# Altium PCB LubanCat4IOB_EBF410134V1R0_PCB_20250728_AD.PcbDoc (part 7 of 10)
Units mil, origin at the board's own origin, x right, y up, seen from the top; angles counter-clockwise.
Board outline 5236.21 x 4055.11 mil, 6 copper layers (TOP, GND02, ART03, PWR04, GND05, BOTTOM), stack 47.2 mil thick; 614 components, 490 nets, 2311 pads, 1916 vias.
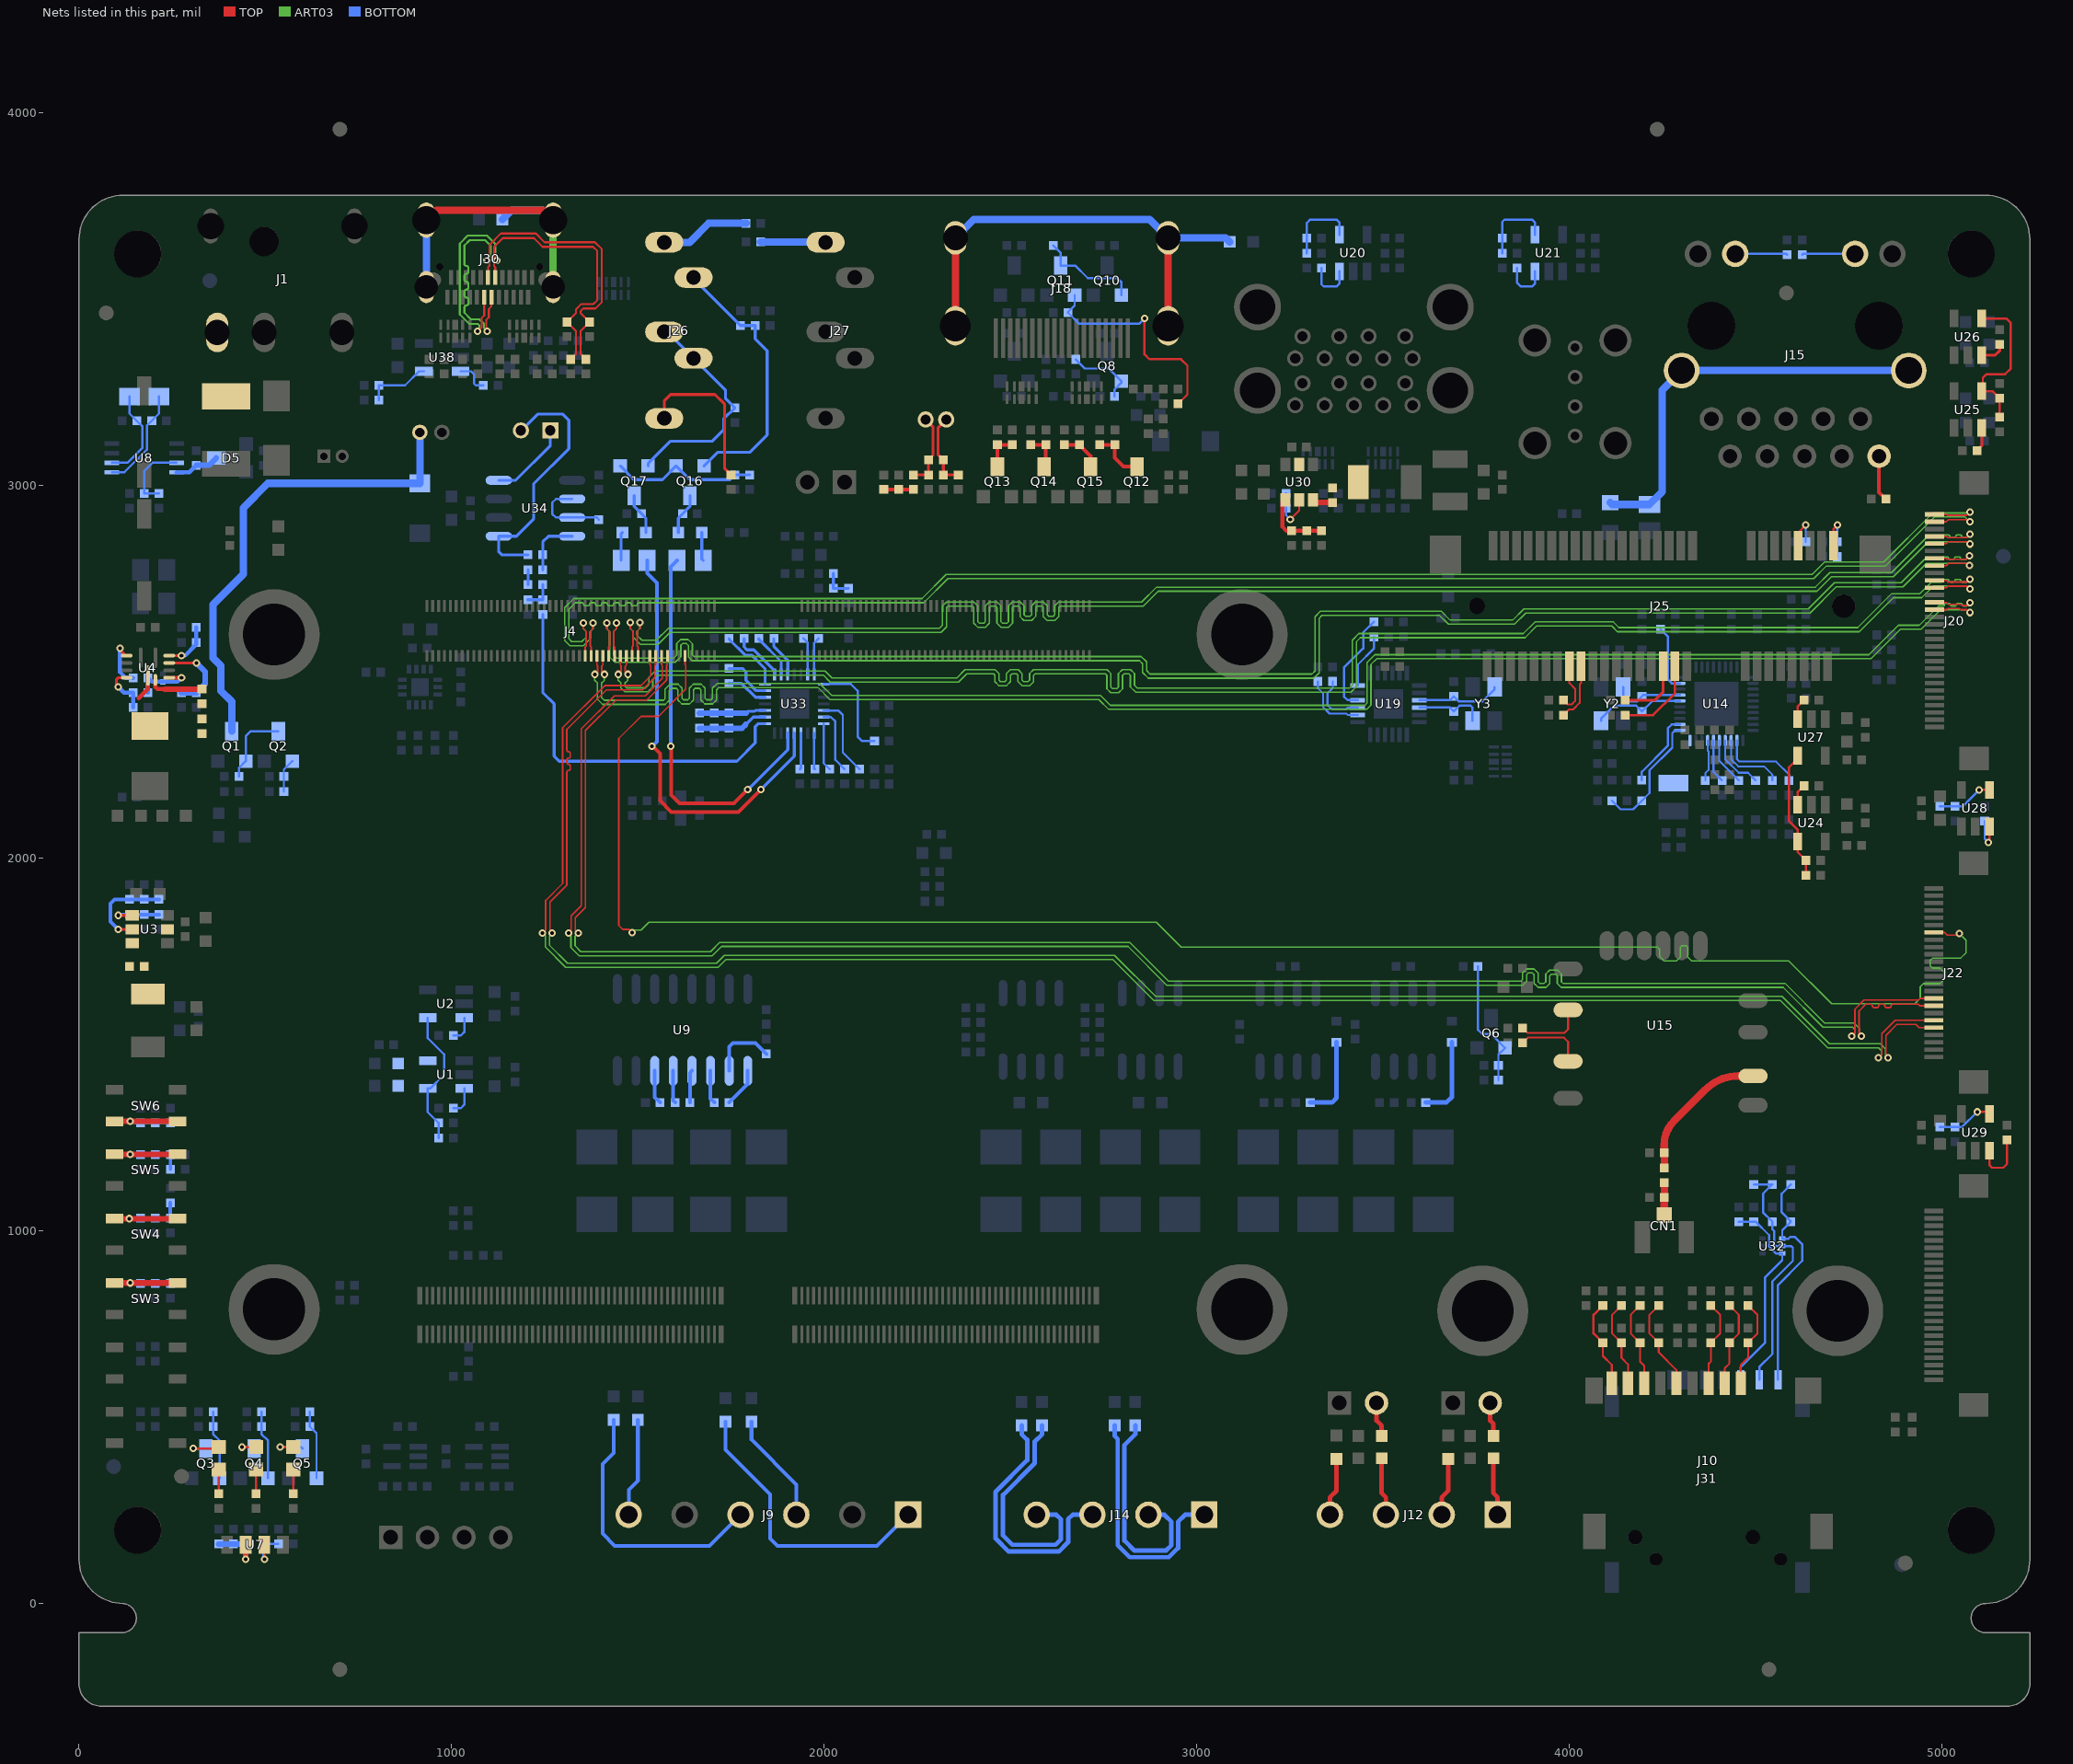
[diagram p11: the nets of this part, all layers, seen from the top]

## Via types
v1: diameter 20, hole 10, TOP to BOTTOM, 1912 vias
v2: diameter 40/50/50/50/50/40 (per signal layer), hole 0, TOP to BOTTOM, 4 vias

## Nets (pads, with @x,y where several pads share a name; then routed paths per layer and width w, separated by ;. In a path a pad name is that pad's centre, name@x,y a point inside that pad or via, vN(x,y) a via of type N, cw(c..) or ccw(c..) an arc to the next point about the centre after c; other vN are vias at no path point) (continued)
MIPI_DPHY1_RX_D1P: J4.89 J22.7 | length 4930.3
  TOP w4.2: v1(1485,1800.77) 1476.6,1809.17 1459.56,1809.17 1448.8,1819.93 1448.8,2321.41 1508.36,2380.97 1555.76,2380.97 1628.74,2453.95 1628.74,2517.7 1626.46,2519.97 J4.89@1626.46,2543.51 ; J22.7@4978.61,1801.18 5007.19,1801.18 5014.74,1793.63 5041.88,1793.63 v1(5046.59,1798.34)
  ART03 w4: v1(1485,1800.77) 1491.6,1807.37 1508.56,1807.37 1529.56,1828.37 2891.44,1828.37 2958.44,1761.37 4236.84,1761.37 4242.6,1755.61 4242.6,1736.41 4254.64,1724.37 4287.68,1724.37 4298.12,1734.81 4298.12,1761.17 4302.12,1765.17 4314.12,1765.17 4318.12,1761.17 4318.12,1734.81 4328.57,1724.37 4589.04,1724.37 4704.04,1609.37 4927.56,1609.37 4942,1623.81 4942,1655.37 4950,1663.37 4994.76,1663.37 5005.2,1673.81 5005.2,1694.93 4994.76,1705.37 4974.6,1705.37 4968.6,1711.37 4968.6,1725.57 4975.4,1732.37 5050.8,1732.37 5064.59,1746.16 5064.59,1780.34 v1(5046.59,1798.34)
MIPI_DPHY1_RX_D2N: J4.83 J22.17 | length 4925.6
  TOP w4.2: v1(1339.8,1799.37) 1332,1807.17 1332,1840.53 1359.4,1867.93 1359.4,2342.97 1441.2,2424.77 1523.99,2424.77 1576.95,2477.72 1576.95,2517.7 1579.22,2519.97 J4.83@1579.22,2543.51 ; v1(4784.1,1522.47) 4777.8,1528.77 4777.8,1590.33 4795.68,1608.21 4809.05,1608.21 cw(c4809.05,1603.69) 4813.57,1603.69 ccw(c4818.09,1603.69) 4818.09,1599.17 4825.85,1599.17 ccw(c4825.85,1603.69) 4830.37,1603.69 cw(c4834.89,1603.69) 4834.89,1608.21 4842.65,1608.21 cw(c4842.65,1603.69) 4847.17,1603.69 ccw(c4851.69,1603.69) 4851.69,1599.17 4859.45,1599.17 ccw(c4859.45,1603.69) 4863.97,1603.69 cw(c4868.49,1603.69) 4868.49,1608.21 4936.56,1608.21 4940.44,1604.33 J22.17@4978.61,1604.33
  ART03 w4: v1(1339.8,1799.37) 1331.3,1790.87 1331.3,1765.07 1347,1749.37 1695,1749.37 1720,1774.37 2820.16,1774.37 2924.16,1670.37 3870.78,1670.37 3874.78,1674.37 3874.78,1692.53 3885.22,1702.97 3905.74,1702.97 3916.78,1691.93 3916.78,1668.37 3920.78,1664.37 3932.78,1664.37 3936.78,1668.37 3936.78,1689.33 3947.22,1699.77 3968.34,1699.77 3978.78,1689.33 3978.78,1668.37 3982.78,1664.37 4578.8,1664.37 4685.8,1557.37 4765,1557.37 4778.6,1543.77 4778.6,1527.97 v1(4784.1,1522.47)
MIPI_DPHY1_RX_D2P: J4.81 J22.16 | length 4925.2
  TOP w4.2: v1(1313.8,1799.37) 1320.8,1806.37 1320.8,1845.17 1348.2,1872.57 1348.2,2347.61 1436.56,2435.97 1519.35,2435.97 1565.75,2482.36 1565.75,2517.7 1563.47,2519.97 J4.81@1563.47,2543.51 ; v1(4758.1,1522.47) 4766.6,1530.97 4766.6,1594.97 4791.04,1619.41 4937.04,1619.41 4941.64,1624.01 J22.16@4978.61,1624.01
  ART03 w4: v1(1313.8,1799.37) 1320.3,1792.87 1320.3,1760.51 1342.44,1738.37 1699.56,1738.37 1724.56,1763.37 2815.6,1763.37 2919.6,1659.37 3875.34,1659.37 3885.78,1669.81 3885.78,1687.97 3889.78,1691.97 3901.18,1691.97 3905.78,1687.37 3905.78,1663.81 3916.22,1653.37 3937.34,1653.37 3947.78,1663.81 3947.78,1684.77 3951.78,1688.77 3963.78,1688.77 3967.78,1684.77 3967.78,1663.81 3978.22,1653.37 4574.24,1653.37 4681.24,1546.37 4760.44,1546.37 4767.6,1539.21 4767.6,1531.97 v1(4758.1,1522.47)
MIPI_DPHY1_RX_D3N: J4.79 J22.20 | length 4930.2
  TOP w4.2: v1(1270,1799.37) 1263.8,1805.57 1263.8,1882.33 1309.4,1927.93 1309.4,2231.04 cw(c1313.9,2231.04) 1313.9,2235.54 ccw(c1313.9,2240.04) 1318.4,2240.04 1318.4,2247.84 ccw(c1313.9,2247.84) 1313.9,2252.34 cw(c1313.9,2256.84) 1309.4,2256.84 1309.4,2264.64 cw(c1313.9,2264.64) 1313.9,2269.14 ccw(c1313.9,2273.64) 1318.4,2273.64 1318.4,2281.44 ccw(c1313.9,2281.44) 1313.9,2285.94 cw(c1313.9,2290.44) 1309.4,2290.44 1309.4,2346.17 1415.4,2452.17 1512.64,2452.17 1545.45,2484.98 1545.45,2517.7 1547.72,2519.97 J4.79@1547.72,2543.51 ; v1(4856,1464.37) 4850.2,1470.17 4850.2,1524.73 4879.23,1553.76 4930.61,1553.76 4939.1,1545.27 J22.20@4978.61,1545.27
  ART03 w4: v1(1270,1799.37) 1262.5,1791.87 1262.5,1766.87 1311,1718.37 1711,1718.37 1732,1739.37 2779.56,1739.37 2889.56,1629.37 4571,1629.37 4698.2,1502.17 4835.03,1502.17 4849,1488.2 4849,1471.37 v1(4856,1464.37)
MIPI_DPHY1_RX_D3P: J4.77 J22.19 | length 4927.4
  TOP w4.2: v1(1244,1799.37) 1252.6,1807.97 1252.6,1886.97 1298.2,1932.57 1298.2,2350.81 1410.76,2463.37 1508,2463.37 1534.25,2489.62 1534.25,2517.7 1531.97,2519.97 J4.77@1531.97,2543.51 ; v1(4830,1464.37) 4839,1473.37 4839,1529.37 4874.59,1564.96 J22.19@4978.61,1564.96
  ART03 w4: v1(1244,1799.37) 1251.5,1791.87 1251.5,1762.31 1306.44,1707.37 1715.56,1707.37 1736.56,1728.37 2775,1728.37 2885,1618.37 4566.44,1618.37 4693.64,1491.17 4830.48,1491.17 4838,1483.65 4838,1472.37 v1(4830,1464.37)
MIPI_DPHY1_TX_CLKN: J4.65 J20.24 | length 4284.1
  TOP w4.2: J4.65@1437.49,2543.51 1437.49,2567.06 1435.21,2569.33 1435.21,2608.39 1442.61,2615.79 v1(1442.61,2631.44) ; J20.24@4980.62,2804.92 5012.08,2804.92 5014.13,2802.87 5065.55,2802.87 5074.5,2811.82 v1(5074.5,2812.22)
  ART03 w4: v1(1442.61,2631.44) 1442.61,2615.81 1435.11,2608.31 1435.11,2544.86 1443.4,2536.57 1595.58,2536.57 1604.38,2545.37 1604.38,2576.73 1614.83,2587.17 1634.94,2587.17 1646.38,2575.73 1646.38,2545.37 1650.38,2541.37 2851,2541.37 2865.4,2526.97 2865.4,2503.37 2874.4,2494.37 3309.4,2494.37 3317.4,2502.37 3317.4,2648.53 3331.84,2662.97 3656.36,2662.97 3680.16,2639.17 3848.24,2639.17 3878.44,2669.37 4641.64,2669.37 4711.64,2739.37 4891,2739.37 4954,2802.37 4999.06,2802.37 ccw(c4999.06,2805.47) 5002.16,2805.47 cw(c5005.26,2805.47) 5005.26,2808.57 5015.06,2808.57 cw(c5015.06,2805.47) 5018.16,2805.47 ccw(c5021.26,2805.47) 5021.26,2802.37 5031.06,2802.37 ccw(c5031.06,2805.47) 5034.16,2805.47 cw(c5037.26,2805.47) 5037.26,2808.57 5047.06,2808.57 cw(c5047.06,2805.47) 5050.16,2805.47 ccw(c5053.26,2805.47) 5053.26,2802.37 5065.19,2802.37 5074.5,2811.68 v1(5074.5,2812.22)
MIPI_DPHY1_TX_CLKP: J4.63 J20.23 | length 4285.9
  TOP w4.2: v1(1416.61,2631.44) 1416.61,2615.79 1424.01,2608.39 1424.01,2569.33 1421.74,2567.06 J4.63@1421.74,2543.51 ; J20.23@4980.62,2785.23 5011.86,2785.23 5018.3,2791.67 5069.05,2791.67 v1(5074.5,2786.22)
  ART03 w4: v1(1416.61,2631.44) 1416.61,2615.81 1424.11,2608.31 1424.11,2540.3 1438.84,2525.57 1600.14,2525.57 1615.38,2540.81 1615.38,2572.17 1619.38,2576.17 1630.38,2576.17 1635.38,2571.17 1635.38,2540.81 1645.83,2530.37 2846.44,2530.37 2854.4,2522.41 2854.4,2498.81 2869.84,2483.37 3313.96,2483.37 3328.4,2497.81 3328.4,2643.97 3336.4,2651.97 3651.8,2651.97 3675.6,2628.17 3852.8,2628.17 3883,2658.37 4646.2,2658.37 4716.2,2728.37 4895.56,2728.37 4958.56,2791.37 5065.71,2791.37 5068.71,2788.37 5070.5,2788.37 5072.65,2786.22 v1(5074.5,2786.22)
MIPI_DPHY1_TX_D0N: J4.73 J20.27 | length 4288.8
  TOP w4.2: J4.73@1500.48,2543.51 1500.48,2567.06 1498.2,2569.33 1498.2,2609.32 1505.61,2616.72 v1(1505.61,2632.37) ; J20.27@4980.62,2863.97 5012.08,2863.97 5015.32,2860.73 5066.36,2860.73 v1(5075,2869.37)
  ART03 w4: v1(1505.61,2632.37) 1505.61,2616.74 1498.11,2609.24 1498.11,2598.37 1511.31,2585.17 1549.64,2585.17 1581.84,2617.37 2309.4,2617.37 2317.4,2625.37 2317.4,2677.13 2328.24,2687.97 2401.85,2687.97 2412.7,2677.13 2412.7,2635.17 2416.7,2631.17 2428.7,2631.17 2432.7,2635.17 2432.7,2677.53 2443.14,2687.97 2463.85,2687.97 2474.7,2677.13 2474.7,2635.17 2478.7,2631.17 2490.7,2631.17 2494.7,2635.17 2494.7,2677.53 2505.14,2687.97 2526.28,2687.97 2536.72,2677.53 2536.72,2653.57 2540.72,2649.57 2552.72,2649.57 2556.72,2653.57 2556.72,2677.53 2567.16,2687.97 2588.28,2687.97 2598.72,2677.53 2598.72,2653.57 2602.72,2649.57 2614.72,2649.57 2618.72,2653.57 2618.72,2677.53 2629.16,2687.97 2852.44,2687.97 2892.04,2727.57 4660.44,2727.57 4699.24,2766.37 4865,2766.37 4959,2860.37 5001.64,2860.37 ccw(c5001.64,2863.97) 5005.24,2863.97 cw(c5008.84,2863.97) 5008.84,2867.57 5017.64,2867.57 cw(c5017.64,2863.97) 5021.24,2863.97 ccw(c5024.84,2863.97) 5024.84,2860.37 5033.64,2860.37 ccw(c5033.64,2863.97) 5037.24,2863.97 cw(c5040.84,2863.97) 5040.84,2867.57 5049.64,2867.57 cw(c5049.64,2863.97) 5053.24,2863.97 ccw(c5056.84,2863.97) 5056.84,2860.37 5066,2860.37 v1(5075,2869.37)
MIPI_DPHY1_TX_D0P: J4.71 J20.26 | length 4289.1
  TOP w4.2: v1(1479.61,2632.37) 1479.61,2616.72 1487.01,2609.32 1487.01,2569.33 1484.73,2567.06 J4.71@1484.73,2543.51 ; J20.26@4980.62,2844.29 5012.08,2844.29 5017.32,2849.53 5068.84,2849.53 v1(5075,2843.37)
  ART03 w4: v1(1479.61,2632.37) 1479.61,2616.74 1487.11,2609.24 1487.11,2593.81 1506.75,2574.17 1554.2,2574.17 1586.4,2606.37 2313.96,2606.37 2328.4,2620.81 2328.4,2672.57 2332.8,2676.97 2397.3,2676.97 2401.7,2672.57 2401.7,2630.61 2412.14,2620.17 2433.25,2620.17 2443.7,2630.61 2443.7,2672.97 2447.7,2676.97 2459.3,2676.97 2463.7,2672.57 2463.7,2630.61 2474.14,2620.17 2495.25,2620.17 2505.7,2630.61 2505.7,2672.97 2509.7,2676.97 2521.72,2676.97 2525.72,2672.97 2525.72,2649.01 2536.16,2638.57 2557.28,2638.57 2567.72,2649.01 2567.72,2672.97 2571.72,2676.97 2583.72,2676.97 2587.72,2672.97 2587.72,2649.01 2598.16,2638.57 2619.28,2638.57 2629.72,2649.01 2629.72,2672.97 2633.72,2676.97 2857,2676.97 2896.6,2716.57 4665,2716.57 4703.8,2755.37 4869.56,2755.37 4963.56,2849.37 5069,2849.37 v1(5075,2843.37)
MIPI_DPHY1_TX_D1N: J4.69 J20.21 | length 4285.3
  TOP w4.2: J4.69@1468.98,2543.51 1468.98,2518.35 1466,2515.37 1466,2497.94 1470.2,2493.74 v1(1473.2,2493.74) ; J20.21@4980.62,2745.86 5012.08,2745.86 5016.32,2741.62 5067.6,2741.62 v1(5075,2749.02)
  ART03 w4: v1(1473.2,2493.74) 1473.2,2478.12 1465.7,2470.62 1465.7,2461.46 1469.7,2457.46 1521.2,2457.46 1529.2,2465.46 1529.2,2485.17 1546.4,2502.37 2002.6,2502.37 2020.8,2484.17 2356.2,2484.17 2378.2,2506.17 2458.88,2506.17 2469.32,2495.73 2469.32,2478.37 2473.32,2474.37 2485.32,2474.37 2489.32,2478.37 2489.32,2495.73 2499.76,2506.17 2520.88,2506.17 2531.32,2495.73 2531.32,2478.37 2535.32,2474.37 2547.32,2474.37 2551.32,2478.37 2551.32,2495.73 2561.76,2506.17 2759.36,2506.17 2769.8,2495.73 2769.8,2459.57 2773.8,2455.57 2785.8,2455.57 2789.8,2459.57 2789.8,2495.53 2800.44,2506.17 2822.56,2506.17 2833,2495.73 2833,2464.37 2841,2456.37 3409.4,2456.37 3417.4,2464.37 3417.4,2585.56 3434.81,2602.97 3876.64,2602.97 3907.84,2634.17 4118.4,2634.17 4133.4,2619.17 4774.2,2619.17 4865.4,2710.37 4941.4,2710.37 4972.55,2741.52 4999.51,2741.52 ccw(c4999.51,2745.05) 5003.04,2745.05 cw(c5006.56,2745.05) 5006.56,2748.57 5015.51,2748.57 cw(c5015.51,2745.05) 5019.04,2745.05 ccw(c5022.56,2745.05) 5022.56,2741.52 5031.51,2741.52 ccw(c5031.51,2745.05) 5035.04,2745.05 cw(c5038.56,2745.05) 5038.56,2748.57 5047.51,2748.57 cw(c5047.51,2745.05) 5051.04,2745.05 ccw(c5054.56,2745.05) 5054.56,2741.52 5067.5,2741.52 v1(5075,2749.02)
MIPI_DPHY1_TX_D1P: J4.67 J20.20 | length 4287.3
  TOP w4.2: v1(1447.2,2493.74) 1450.6,2493.74 1454.8,2497.94 1454.8,2516.99 1453.23,2518.55 J4.67@1453.23,2543.51 ; J20.20@4980.62,2726.18 5012.08,2726.18 5016.32,2730.42 5067.6,2730.42 v1(5075,2723.02)
  ART03 w4: v1(1447.2,2493.74) 1447.2,2478.12 1454.7,2470.62 1454.7,2456.9 1465.15,2446.46 1525.76,2446.46 1540.2,2460.9 1540.2,2480.61 1550.96,2491.37 1998.04,2491.37 2016.24,2473.17 2360.76,2473.17 2382.76,2495.17 2454.32,2495.17 2458.32,2491.17 2458.32,2473.81 2468.76,2463.37 2489.88,2463.37 2500.32,2473.81 2500.32,2491.17 2504.32,2495.17 2516.32,2495.17 2520.32,2491.17 2520.32,2473.81 2530.76,2463.37 2551.88,2463.37 2562.32,2473.81 2562.32,2491.17 2566.32,2495.17 2754.8,2495.17 2758.8,2491.17 2758.8,2455.01 2769.24,2444.57 2790.36,2444.57 2800.8,2455.01 2800.8,2490.97 2805,2495.17 2818,2495.17 2822,2491.17 2822,2459.81 2836.44,2445.37 3413.96,2445.37 3428.4,2459.81 3428.4,2581 3439.37,2591.97 3881.2,2591.97 3912.4,2623.17 4113.84,2623.17 4128.84,2608.17 4778.76,2608.17 4869.96,2699.37 4945.96,2699.37 4977.11,2730.52 5067.5,2730.52 v1(5075,2723.02)
MIPI_DPHY1_TX_D2N: J4.61 J20.18 | length 4281.6
  TOP w4.2: J4.61@1405.99,2543.51 1405.99,2518.35 1403.01,2515.37 1403.01,2497.94 1407.21,2493.74 v1(1410.21,2493.74) ; J20.18@4980.62,2686.81 5012.08,2686.81 5017.32,2681.57 5051.64,2681.57 5054.64,2678.57 5068.2,2678.57 v1(5075,2685.37)
  ART03 w4: v1(1410.21,2493.74) 1410.21,2478.12 1402.71,2470.62 1402.71,2431.22 1409.96,2423.97 1568.8,2423.97 1572.8,2427.97 1572.8,2453.93 1586.04,2467.17 1607.91,2467.17 1618.35,2456.73 1618.35,2429.17 1622.35,2425.17 1634.15,2425.17 1638.35,2429.37 1638.35,2456.73 1648.8,2467.17 1669.91,2467.17 1680.35,2456.73 1680.35,2429.17 1684.35,2425.17 1696.15,2425.17 1700.35,2429.37 1700.35,2456.73 1713,2469.37 1988,2469.37 2020.2,2437.17 2741.8,2437.17 2768.4,2410.57 3451.64,2410.57 3456.8,2415.73 3456.8,2524.73 3478.44,2546.37 4804.44,2546.37 4883.44,2625.37 4939.44,2625.37 4991.34,2677.27 5003.6,2677.27 ccw(c5003.6,2680.42) 5006.75,2680.42 cw(c5009.9,2680.42) 5009.9,2683.57 5019.6,2683.57 cw(c5019.6,2680.42) 5022.75,2680.42 ccw(c5025.9,2680.42) 5025.9,2677.27 5035.6,2677.27 ccw(c5035.6,2680.42) 5038.75,2680.42 cw(c5041.9,2680.42) 5041.9,2683.57 5051.6,2683.57 cw(c5051.6,2680.42) 5054.75,2680.42 ccw(c5057.9,2680.42) 5057.9,2677.27 5066.9,2677.27 v1(5075,2685.37)
MIPI_DPHY1_TX_D2P: J4.59 J20.17 | length 4284.5
  TOP w4.2: v1(1384.21,2493.74) 1387.61,2493.74 1391.81,2497.94 1391.81,2516.99 1390.24,2518.55 J4.59@1390.24,2543.51 ; J20.17@4980.62,2667.12 5012.08,2667.12 5015.32,2670.37 5047,2670.37 5050,2667.37 5067,2667.37 v1(5075,2659.37)
  ART03 w4: v1(1384.21,2493.74) 1384.21,2478.12 1391.71,2470.62 1391.71,2426.66 1405.4,2412.97 1573.36,2412.97 1583.8,2423.41 1583.8,2449.37 1590.6,2456.17 1603.35,2456.17 1607.35,2452.17 1607.35,2424.61 1617.8,2414.17 1638.71,2414.17 1649.35,2424.81 1649.35,2452.17 1653.35,2456.17 1665.15,2456.17 1669.15,2452.17 1669.15,2424.61 1679.6,2414.17 1700.71,2414.17 1711.35,2424.81 1711.35,2452.17 1717.55,2458.37 1983.44,2458.37 2015.64,2426.17 2737.24,2426.17 2763.84,2399.57 3456.2,2399.57 3467.8,2411.17 3467.8,2520.17 3483,2535.37 4809,2535.37 4888,2614.37 4944,2614.37 4995.9,2666.27 5068.1,2666.27 v1(5075,2659.37)
MIPI_DPHY1_TX_D3N: J4.57 J20.30 | length 4285.1
  TOP w4.2: J4.57@1374.49,2543.51 1374.49,2567.06 1372.22,2569.33 1372.22,2608.39 1379.62,2615.79 v1(1379.62,2631.44) ; J20.30@4980.62,2923.03 5012.08,2923.03 5014.83,2920.29 5065.92,2920.29 v1(5075,2929.37)
  ART03 w4: v1(1379.62,2631.44) 1379.62,2615.81 1372.12,2608.31 1372.12,2588.81 1353.68,2570.37 1317.84,2570.37 1303.4,2584.81 1303.4,2672.73 1327.64,2696.97 2262.6,2696.97 2327.4,2761.77 4651.84,2761.77 4685.44,2795.37 4844,2795.37 4975.32,2926.69 5072.32,2926.69 v1(5075,2929.37)
MIPI_DPHY1_TX_D3P: J4.55 J20.29 | length 4283.4
  TOP w4.2: v1(1353.62,2631.44) 1353.62,2615.79 1361.02,2608.39 1361.02,2569.33 1358.75,2567.06 J4.55@1358.75,2543.51 ; J20.29@4980.62,2903.34 5012.08,2903.34 5017.83,2909.09 5069.28,2909.09 v1(5075,2903.37)
  ART03 w4: v1(1353.62,2631.44) 1353.62,2615.81 1361.12,2608.31 1361.12,2593.37 1349.12,2581.37 1322.4,2581.37 1314.4,2589.37 1314.4,2668.17 1332.2,2685.97 1350.09,2685.97 cw(c1350.09,2681.67) 1354.39,2681.67 ccw(c1358.69,2681.67) 1358.69,2677.37 1366.09,2677.37 ccw(c1366.09,2681.67) 1370.39,2681.67 cw(c1374.69,2681.67) 1374.69,2685.97 1382.09,2685.97 cw(c1382.09,2681.67) 1386.39,2681.67 ccw(c1390.69,2681.67) 1390.69,2677.37 1398.09,2677.37 ccw(c1398.09,2681.67) 1402.39,2681.67 cw(c1406.69,2681.67) 1406.69,2685.97 1414.09,2685.97 cw(c1414.09,2681.67) 1418.39,2681.67 ccw(c1422.69,2681.67) 1422.69,2677.37 1430.09,2677.37 ccw(c1430.09,2681.67) 1434.39,2681.67 cw(c1438.69,2681.67) 1438.69,2685.97 1446.09,2685.97 cw(c1446.09,2681.67) 1450.39,2681.67 ccw(c1454.69,2681.67) 1454.69,2677.37 1462.09,2677.37 ccw(c1462.09,2681.67) 1466.39,2681.67 cw(c1470.69,2681.67) 1470.69,2685.97 1478.09,2685.97 cw(c1478.09,2681.67) 1482.39,2681.67 ccw(c1486.69,2681.67) 1486.69,2677.37 1494.09,2677.37 ccw(c1494.09,2681.67) 1498.39,2681.67 cw(c1502.69,2681.67) 1502.69,2685.97 2267.16,2685.97 2331.96,2750.77 4656.4,2750.77 4690,2784.37 4848.56,2784.37 4979.87,2915.69 5062.68,2915.69 v1(5075,2903.37)
N02088: F1.1 J1.4
N03633: C9.1 U3.6
N03641: C9.2 L1.1 U3.2
N03801: C10.2 R6.2 R7.1 U3.4 | length 148.7
  TOP w8: v1(105,1846.77) U3.4@142.76,1846.77
  BOTTOM w10: v1(105,1846.77) 107.28,1849.05 R7.1@135,1849.05 R6.2@175,1849.05 C10.2@215,1849.05
N15118646: R1.2 R2.2 U1.5
N15118698: C4.1 R3.2 U1.4 U2.4 | length 375.4
  BOTTOM w6: U2.4@935.79,1571.97 935.79,1517.58 980,1473.36 980,1419.37 942.6,1381.97 U1.4@935.79,1381.97 935.79,1318.9 C4.1@965.32,1289.37 R3.2@965.32,1249.37
N15119063: R4.1 U1.3 | length 76.7
  BOTTOM w6: R4.1@1004.68,1329.37 1025,1329.37 1034.21,1338.58 U1.3@1034.21,1381.97
N15123057: R5.1 U2.3 | length 71.7
  BOTTOM w6: R5.1@1004.68,1524.37 1025,1524.37 1034.21,1533.58 U2.3@1034.21,1571.97
N15599533: R84.2 U14.25 | length 128.5
  BOTTOM w5.2: U14.25@4402.87,2315.94 4402.87,2261.18 R84.2@4455,2209.05
N15599537: R85.2 U14.24 | length 155.1
  BOTTOM w5.2: U14.24@4418.62,2315.94 4418.62,2265.75 4454.92,2229.45 4479.6,2229.45 R85.2@4500,2209.05
N15599541: R87.2 U14.23 | length 193.2
  BOTTOM w5.2: U14.23@4434.37,2315.94 4434.37,2265.84 4453.64,2246.57 4522.8,2246.57 4545,2224.37 R87.2@4545,2209.05
N15599545: R88.2 U14.22 | length 222.4
  BOTTOM w5.2: U14.22@4450.12,2315.94 4450.12,2265.93 4456.68,2259.37 4555,2259.37 4590,2224.37 R88.2@4590,2209.05
N15599549: R89.2 U14.27 | length 111.4
  BOTTOM w5.2: R89.2@4365,2209.05 4365,2228.45 4373.6,2237.05 4373.6,2287.08 4371.38,2289.29 U14.27@4371.38,2315.94
N15599553: R90.2 U14.26 | length 116.4
  BOTTOM w5.2: U14.26@4387.13,2315.94 4387.13,2231.92 R90.2@4410,2209.05
N15600826: R95.2 R96.2 U14.31 | length 337.7
  BOTTOM w6: R96.2@4114.68,2154.37 4137.68,2131.37 4171.68,2131.37 R95.2@4194.68,2154.37 4215.48,2175.17 4215.48,2235.91 4276.5,2296.93 4276.5,2335.87 4284.13,2343.5 U14.31@4296.57,2343.5
N15601838: C74.1 U14.37 Y2.1 | length 192.2
  BOTTOM w6: Y2.1@4144.53,2459.65 4144.53,2429.84 4153,2421.37 4181.68,2421.37 C74.1@4195,2434.69 4198.3,2437.99 U14.37@4296.57,2437.99
N15601846: C75.1 U14.36 Y2.3 | length 249.2
  BOTTOM w6: Y2.3@4085.47,2369.09 4085.47,2374.84 4120,2409.37 4179.68,2409.37 C75.1@4195,2394.05 4223.19,2422.24 U14.36@4296.57,2422.24
N15602572: R104.1 U14.32 | length 204.8
  BOTTOM w6: R104.1@4194.68,2209.37 4194.68,2232.08 4264.5,2301.9 4264.5,2348.87 4274.88,2359.25 U14.32@4296.57,2359.25
N15603170: C76.1 J15.1 | length 122.3
  TOP w10: J15.1@4831.49,3079.13 4831.49,2982.56 C76.1@4849.68,2964.37
N15603215: C77.1 J15.15 J15.16 R101.1 | length 1112.3
  BOTTOM w20: R101.1@4110,2954.37 4114.96,2949.41 C77.1@4215,2949.41 4249,2983.41 4249,3256.68 J15.16@4301.37,3309.05 J15.15@4911.21,3309.05
N15604636: J15.12 R100.1 | length 143.1
  BOTTOM w6: R100.1@4625,3619.69 4627.36,3622.05 J15.12@4767.12,3622.05
N15605512: R86.1 U14.39 | length 179.3
  BOTTOM w6: R86.1@4245,2614.69 4265,2594.69 4265,2479.37 4274.88,2469.49 U14.39@4296.57,2469.49
N15611443: C100.1 R118.2 U20.4 | length 208.4
  BOTTOM w6: R118.2@3295,3624.05 3295,3664.05 C100.1@3295.32,3664.37 3295.32,3704.69 3305,3714.37 3375,3714.37 3382.6,3706.77 U20.4@3382.6,3673.58
N15611553: R121.1 U20.3 | length 130.7
  BOTTOM w6: R121.1@3335,3584.69 3335,3540.37 3341,3534.37 3375,3534.37 3382.6,3541.97 U20.3@3382.6,3575.16
N15654067: R125.1 U21.3 | length 128.4
  BOTTOM w6: R125.1@3860,3584.69 3860,3544.37 3870,3534.37 3900,3534.37 3907.6,3541.97 U21.3@3907.6,3575.16
N15659726: C18.2 R8.2 R9.1 U3.5 | length 251.1
  TOP w8: v1(105,1809.37) U3.5@142.76,1809.37
  BOTTOM w10: v1(105,1809.37) 84,1830.37 84,1878.37 95.32,1889.69 C18.2@135,1889.69 R9.1@175,1889.69 R8.2@215,1889.69
N15752445: J18.G1 J18.G2 J18.G3 J18.G4 L5.1 | length 1253.8
  TOP w20: J18.G1@2352.36,3429.02 J18.G3@2352.36,3665.24 ; J18.G2@2923.22,3429.02 J18.G4@2923.22,3665.24
  BOTTOM w20: J18.G3@2352.36,3665.24 2401.49,3714.37 2874.09,3714.37 J18.G4@2923.22,3665.24 3077.63,3665.24 L5.1@3088.5,3654.37
N16793147: D11.2 J10.1 R53.2 | length 237.7
  TOP w5.2: J10.1@4460.62,590.75 4460.62,639.99 4480,659.37 D11.2@4480,699.69 4505,724.69 4505,774.69 R53.2@4480,799.69
N16793149: D15.2 J10.7 R58.2 | length 234.1
  TOP w5.2: R58.2@4190,799.69 4165,774.69 4165,724.69 D15.2@4190,699.69 4190,649.37 4200.78,638.59 J10.7@4200.78,590.75
N16793151: D14.2 J10.5 R57.2 | length 249.3
  TOP w5.2: R57.2@4240,799.69 4215,774.69 4215,724.69 D14.2@4240,699.69 4240,674.37 4287.39,626.99 J10.5@4287.39,590.75
N16793153: D13.2 J10.3 R55.2 | length 232.1
  TOP w5.2: J10.3@4374.01,590.75 4374.01,643.38 4380,649.37 D13.2@4380,699.69 4405,724.69 4405,774.69 R55.2@4380,799.69
N16793155: D12.2 J10.2 R54.2 | length 234.9
  TOP w5.2: J10.2@4417.31,590.75 4417.31,631.68 4430,644.37 D12.2@4430,699.69 4455,724.69 4455,774.69 R54.2@4430,799.69
N16793157: D16.2 J10.8 R59.2 | length 236.9
  TOP w5.2: R59.2@4140,799.69 4115,774.69 4115,724.69 D16.2@4140,699.69 4140,659.37 4157.47,641.9 J10.8@4157.47,590.75
N16793300: D17.2 J10.9 R60.2 | length 239.7
  TOP w6: R60.2@4090,799.69 4065,774.69 4065,724.69 D17.2@4090,699.69 4090,664.37 4114.16,640.21 J10.9@4114.16,590.75
N16811933: J25.1 R177.2 R178.2 | length 145.6
  TOP w6: J25.1@4708.8,2838.58 4708.8,2883.17 v1(4720,2894.37)
  BOTTOM w6: R177.2@4719.68,2809.37 R178.2@4719.68,2849.37 4719.68,2894.05 v1(4720,2894.37)
N16823854: J25.7 R179.2 | length 109.5
  TOP w6: J25.7@4614.32,2838.58 4614.32,2873.69 v1(4635,2894.37)
  BOTTOM w6: R179.2@4634.68,2849.37 4634.68,2894.05 v1(4635,2894.37)
N16928945: J25.20 R180.1 | length 231
  TOP w6: R180.1@4149.68,2384.37 4225,2384.37 4283.61,2442.98 J25.20@4283.61,2515.74
N16929135: J25.22 R181.1 | length 180.9
  TOP w8: R181.1@4149.68,2424.37 4230,2424.37 4252.11,2446.48 J25.22@4252.11,2515.74
N16980859: C155.1 J31.2 R170.2 U32.6 | length 555.3
  BOTTOM w6: R170.2@4455,1024.69 C155.1@4495,1024.69 4500.28,1024.69 4536.28,988.69 4536.28,958.12 4554.72,939.68 U32.6@4571.57,939.68 4571.57,920.95 4525,874.37 4525,699.37 4460.23,634.6 J31.2@4460.23,600.19
N16980861: C154.1 J31.3 R171.2 U32.4 | length 630.7
  BOTTOM w6: J31.3@4560.23,600.19 4560.23,854.6 4625,919.37 4625,964.37 4605.31,984.05 4593.43,984.05 4588.43,979.05 U32.4@4571.57,979.05 4571.57,1001.26 C154.1@4595,1024.69 4570,1049.69 4570,1099.69 R171.2@4595,1124.69
N16980863: C153.1 J31.7 R169.2 R173.2 U32.5 | length 678.8
  BOTTOM w6: R173.2@4495,1124.69 R169.2@4545,1124.69 4520,1099.69 4520,1049.69 C153.1@4545,1024.69 4545,1004.37 4550,999.37 4550,964.09 4554.72,959.37 U32.5@4571.57,959.37 4595,959.37 4600,954.37 4600,919.37 4545,864.37 4545,669.37 4510.23,634.6 J31.7@4510.23,600.19
N17454508: C56.2 U9.1 | length 106
  BOTTOM w10: C56.2@1744.68,1344.37 1794.8,1394.49 U9.1@1794.8,1429.57
N17454513: C56.1 U9.3 | length 89.6
  BOTTOM w10: U9.3@1694.8,1429.57 1694.8,1354.89 C56.1@1705.32,1344.37
N17455367: C57.2 U9.4 | length 87.5
  BOTTOM w10: C57.2@1639.68,1344.37 1639.68,1424.05 U9.4@1645.2,1429.57
N17455372: C57.1 U9.5 | length 87.5
  BOTTOM w10: U9.5@1594.8,1429.57 1594.8,1349.89 C57.1@1600.32,1344.37
N17455499: C55.1 U9.6 | length 91.2
  BOTTOM w10: U9.6@1545.2,1429.57 1545.2,1358.85 C55.1@1559.68,1344.37
N17455508: C53.1 U9.2 | length 181
  BOTTOM w10: U9.2@1745.2,1429.57 1745.2,1494.37 1755.2,1504.37 1815.32,1504.37 C53.1@1845,1474.69
N17466585: L3.1 U14.30
N17592125: C145.1 U30.6 | length 55.7
  TOP w15: U30.6@3312.4,2962.13 3319.84,2954.69 C145.1@3365,2954.69
N17592129: C145.2 L6.1 U30.2
N17592172: C146.2 R172.2 R174.1 U30.4 | length 185.4
  TOP w10: U30.4@3237.6,2962.13 3230,2954.53 3230,2889.05 3240,2879.05 R174.1@3255,2879.05 R172.2@3295,2879.05 C146.2@3335,2879.05
N17592220: R175.2 R176.1 U30.5 | length 137.4
  TOP w6: v1(3251,2909.37) 3275,2933.37 U30.5@3275,2962.13
  BOTTOM w6: R175.2@3239.68,2979.37 R176.1@3239.68,2939.37 3239.68,2920.69 v1(3251,2909.37)
N17633217: C103.1 U19.3 Y3.1 | length 230.9
  BOTTOM w6: U19.3@3597.68,2424.21 3679.52,2424.21 C103.1@3690,2434.69 3703.32,2421.37 3767,2421.37 3799.53,2453.9 Y3.1@3799.53,2459.65
N17633237: C102.2 U19.4 Y3.3 | length 190.5
  BOTTOM w6: U19.4@3597.68,2404.53 3679.52,2404.53 C102.2@3690,2394.05 3705.32,2409.37 3735,2409.37 3740.47,2403.9 Y3.3@3740.47,2369.09
N17633305: R123.2 U19.18 | length 148.6
  BOTTOM w6: U19.18@3432.32,2463.58 3432.32,2519.69 3475.32,2562.69 R123.2@3475.32,2594.37
N17633317: R122.2 U19.16 | length 274.8
  BOTTOM w6: U19.16@3432.32,2424.21 3405.16,2424.21 3395,2434.37 3395,2511.37 3447,2563.37 3447,2606.05 R122.2@3475.32,2634.37
N17695706: C128.1 R156.2 U25.4 U26.4 | length 433.1
  TOP w6: U26.4@5107.4,3448.58 5173,3448.58 5185,3436.58 5185,3314.37 5170,3299.37 5120,3299.37 5110,3289.37 5110,3256.18 U25.4@5107.4,3253.58 5136.11,3253.58 C128.1@5155,3234.69 R156.2@5155,3184.05
N17695791: R159.1 U26.3 | length 70.1
  TOP w8: U26.3@5107.4,3350.16 5143,3350.16 5155,3362.16 R159.1@5155,3379.69
N17695827: R158.1 U25.3 | length 66.1
  TOP w8: R158.1@5094.68,3094.37 5107.4,3107.09 U25.3@5107.4,3155.16
N17697466: J15.13 R99.1 | length 140.5
  BOTTOM w6: J15.13@4445.46,3622.05 4582.64,3622.05 R99.1@4585,3619.69
N17697880: R166.1 U28.3 | length 104.9
  TOP w6: v1(5125.12,2042.56) 5127.4,2044.84 U28.3@5127.4,2085.16
  BOTTOM w6: R166.1@5115,2099.69 5115,2052.68 v1(5125.12,2042.56)
N17697953: C139.1 R165.2 U28.4 | length 150.8
  TOP w6: v1(5100,2183.58) U28.4@5127.4,2183.58
  BOTTOM w6: R165.2@4995,2139.05 C139.1@5035,2139.05 5055.47,2139.05 v1(5100,2183.58)
N17702194: J12.3 R68.2 | length 155.8
  TOP w12: R68.2@3496.5,389.37 3496.5,295.79 3507.67,284.62 J12.3@3507.67,238.19
N17702199: J12.4 R69.2 | length 156.9
  TOP w12: J12.4@3357.67,238.19 3357.67,284.62 3375,301.95 R69.2@3375,387.87
N17702222: J12.2 R67.2 | length 156.9
  TOP w12: J12.2@3657.67,238.19 3657.67,284.62 3675,301.95 R67.2@3675,387.87
N17702231: J12.1 R66.2 | length 155.8
  TOP w12: R66.2@3796.5,389.37 3796.5,295.79 3807.67,284.62 J12.1@3807.67,238.19
N17728858: D19.1 R62.1 | length 223.6
  BOTTOM w12: R62.1@3614.68,1344.37 3670,1344.37 3685,1359.37 D19.1@3685,1506.42
N17729021: D23.1 R70.1 | length 225.3
  BOTTOM w12: R70.1@3304.68,1344.37 3363,1344.37 3375,1356.37 D23.1@3375,1506.42
N17731608: J9.4 R51.2 | length 736.7
  BOTTOM w10: R51.2@1435,492.87 1435,404.37 1405,374.37 1405,187.37 1438,154.37 1691.57,154.37 J9.4@1775.39,238.19
N17731627: J9.1 R49.2 | length 776.6
  BOTTOM w10: R49.2@1735,487.87 1735,412.37 1855,292.37 1855,174.37 1875,154.37 2141.57,154.37 J9.1@2225.39,238.19
N17750545: Q1.1 Q2.3 R12.2 | length 208.8
  BOTTOM w6: R12.2@429.68,2219.37 429.68,2243.05 Q1.1@447.5,2260.87 447.5,2327.87 460.5,2340.87 Q2.3@535,2340.87
N17750554: D2.1 J2.1 Q1.3 | length 1291.7
  BOTTOM w20: Q1.3@410,2340.87 410,2420.37 381,2449.37 381,2517 360,2538 360,2681 441,2762 441,2940.37 506.93,3006.3 D2.1@915,3006.3 J2.1@915,3142.9
N17750632: Q2.1 R13.2 R16.1 | length 91
  BOTTOM w6: R13.2@549.68,2179.37 R16.1@549.68,2219.37 549.68,2238.05 Q2.1@572.5,2260.87
N17770939: R119.1 U19.15 | length 156.4
  BOTTOM w5.3: R119.1@3365,2474.69 3365,2456.79 3351.15,2442.94 3351.15,2411.22 3361.75,2400.62 3401.02,2400.62 3404.93,2404.53 U19.15@3432.32,2404.53
N17770942: R120.1 U19.14 | length 176.6
  BOTTOM w5.3: R120.1@3325,2474.69 3325,2456.79 3338.85,2442.94 3338.85,2406.13 3356.66,2388.32 3401.45,2388.32 3404.93,2384.84 U19.14@3432.32,2384.84
N17946485: C43.1 R28.1 SW3.3 SW3.4 Z5.2 | length 277.2
  TOP w15: SW3.3@95.35,860.19 v1(137.52,860.19) SW3.4@264.65,860.19
  BOTTOM w10: v1(137.52,860.19) 138.66,859.05 Z5.2@165,859.05 C43.1@205,859.05 R28.1@245,859.05
N18056005: C94.2 Q6.1 R110.2 R111.2 | length 356.6
  BOTTOM w6: R111.2@3754.68,1709.37 3754.68,1539.69 3766,1528.37 3790,1528.37 Q6.1@3827.5,1490.87 3809.68,1473.05 C94.2@3809.68,1444.37 R110.2@3809.68,1404.37
N18056634: C91.1 C92.1 U15.2 | length 389.4
  TOP w20: C91.1@4255.32,1169.05 4255.32,1209.05 C92.1@4255,1209.37 4255,1232.37 cw(c4341.91,1232.37) 4280.46,1293.83 4365.84,1379.21 cw(c4454.25,1290.81) 4454.25,1415.83 U15.2@4493.03,1415.83
N18056637: C91.2 C93.1 CN1.1 | length 87.6
  TOP w20: CN1.1@4255,1042.22 C93.1@4255,1089.37 4255.32,1089.69 C91.2@4255.32,1129.69
N18057251: J25.36 R182.1 | length 156.9
  TOP w5.3: R182.1@3984.68,2384.37 3999.68,2399.37 4010,2399.37 4027.86,2417.23 4027.86,2466.5 4031.64,2470.28 J25.36@4031.64,2515.74
N18057253: J25.38 R183.1 | length 139.2
  TOP w5.3: R183.1@3984.68,2424.37 3995.95,2413.09 4006.33,2413.09 4015.56,2422.32 4015.56,2454.86 4000.14,2470.28 J25.38@4000.14,2515.74
N18057325: R109.2 U15.7 | length 183.9
  TOP w5.3: R109.2@3874.68,1544.37 3888.17,1530.88 3986.51,1530.88 3996.97,1541.34 U15.7@3996.97,1592.99
N18057335: R108.2 U15.6 | length 185
  TOP w5.3: R108.2@3874.68,1504.37 3888.89,1518.58 3985.79,1518.58 3996.97,1507.4 U15.6@3996.97,1455.2
N18111918: C125.1 R155.2 U24.4 U27.4 | length 348.9
  TOP w6: U27.4@4612.6,2275.16 4612.6,2266.97 4590,2244.37 4590,2099.37 4612.6,2076.77 U24.4@4612.6,2045.16 4612.6,2017.09 C125.1@4635.32,1994.37 R155.2@4635.32,1954.37
N18111989: R160.1 U27.3 | length 58.1
  TOP w6: U27.3@4612.6,2373.58 4612.6,2406.65 R160.1@4630.32,2424.37
N18112037: R157.1 U24.3 | length 58.1
  TOP w6: U24.3@4612.6,2143.58 4612.6,2176.65 R157.1@4630.32,2194.37
N18115454: R168.1 U29.3 | length 158.4
  TOP w6: U29.3@5127.4,1215.16 5127.4,1176.97 5135,1169.37 5165,1169.37 5175,1179.37 R168.1@5175,1244.69
N18115527: C142.1 R167.2 U29.4 | length 151.5
  TOP w6: v1(5095,1319.37) 5121.61,1319.37 U29.4@5127.4,1313.58
  BOTTOM w6: R167.2@4995,1279.05 C142.1@5035,1279.05 5054.68,1279.05 v1(5095,1319.37)
N18211307: C30.1 R19.1 R21.1 U4.9 | length 172.4
  TOP w10: U4.9@242.09,2484.84 274.69,2484.84 v1(275,2484.53)
  BOTTOM w11: R21.1@184.68,2444.37 R19.1@184.68,2484.37 195.51,2473.54 C30.1@225,2473.54 264.01,2473.54 v1(275,2484.53)
N18211553: C20.2 L2.1 U4.7 | length 71.7
  TOP w11: 160,2429.37 185,2454.37 U4.7@185,2490.75
N18211596: R19.2 U4.3 | length 134.4
  TOP w8: v1(110,2563.66) 110,2559.37 125.47,2543.9 U4.3@127.91,2543.9
  BOTTOM w11: v1(110,2563.66) 110,2499.37 125,2484.37 R19.2@145.32,2484.37
N18211602: R21.2 R22.2 U4.6 | length 137.9
  TOP w8: v1(105.5,2459.87) 100,2465.37 100,2478.84 106,2484.84 U4.6@127.91,2484.84
  BOTTOM w11: v1(105.5,2459.87) 121,2444.37 R21.2@145.32,2444.37 R22.2@145.32,2404.37
N18211651: R18.2 R20.1 U4.11 | length 212.8
  TOP w8: U4.11@242.09,2524.21 266.4,2524.21 266.71,2523.9 283.29,2523.9 283.6,2524.21 v1(315,2524.21)
  BOTTOM w15: R20.1@275,2444.05 R18.2@315,2444.05 338.5,2467.55 338.5,2500.71 v1(315,2524.21)
N18211688: R14.1 U4.8 | length 146.9
  TOP w11: U4.8@204.69,2478.94 204.69,2459.68 210.32,2454.05 229.57,2454.05
  TOP w15: 229.57,2454.05 R14.1@330,2454.05
N18211692: C20.1 R14.2
N18213641: R15.2 R17.2 U4.12 | length 130.4
  TOP w8: U4.12@242.09,2543.9 v1(275,2543.9)
  BOTTOM w11: v1(275,2543.9) 284.53,2543.9 314.68,2574.05 R17.2@314.68,2579.37 R15.2@314.68,2619.37
N18241743: J30.1 J30.2 J30.3 J30.4 L7.1 | length 878
  TOP w20: J30.3@932.28,3712.59 959.06,3739.37 1245.66,3739.37 J30.2@1272.44,3712.59
  ART03 w20: J30.1@1272.44,3533.46 J30.2@1272.44,3712.59
  BOTTOM w20: J30.4@932.28,3533.46 J30.3@932.28,3712.59 ; L7.1@1136.5,3714.37 1161.5,3739.37 1245.66,3739.37 J30.2@1272.44,3712.59
N18284542: C123.1 Q8.1 R130.2 | length 195.5
  BOTTOM w6: R130.2@2675,3339.05 2699.68,3314.37 2764,3314.37 Q8.1@2797.5,3280.87 2797.5,3275.87 2779.68,3258.05 C123.1@2779.68,3239.37
N18285221: Q10.1 Q11.3 R135.2 | length 278.4
  BOTTOM w6: R135.2@2615.32,3644.37 2635,3624.69 Q11.3@2635,3590.87 2673.5,3590.87 2707.5,3556.87 2787.5,3556.87 2797.5,3546.87 Q10.1@2797.5,3510.87
N18285616: Q11.1 R139.1 R142.1 | length 615.8
  TOP w6: v1(2860,3449.37) 2860,3352.37 2873,3339.37 2958,3339.37 2975,3322.37 2975,3244.69 R139.1@2949.68,3219.37
  BOTTOM w6: Q11.1@2672.5,3510.87 2672.5,3483.74 2654.68,3465.92 R142.1@2654.68,3464.37 2684.68,3434.37 2845,3434.37 v1(2860,3449.37)
N18287294: Q15.3 R134.2 R136.2 | length 111.2
  TOP w10: R134.2@2645,3109.69 R136.2@2685,3109.69 2715,3079.69 Q15.3@2715,3050.87
N18287307: Q14.3 R137.2 R138.2 | length 100.9
  TOP w10: R137.2@2555,3109.69 R138.2@2595,3109.69 2595,3055.87 Q14.3@2590,3050.87
N18287331: Q13.3 R140.2 R141.2 | length 98.8
  TOP w10: Q13.3@2465,3050.87 R140.2@2465,3109.69 R141.2@2505,3109.69
N18287355: Q12.3 R143.2 R144.2 | length 145.1
  TOP w10: R143.2@2740,3109.69 R144.2@2780,3109.69 2780,3074.37 2803.5,3050.87 Q12.3@2840,3050.87
N18312149: R198.2 U33.27 | length 100.9
  BOTTOM w6: R198.2@1945,2589.69 1955.43,2579.26 U33.27@1955.43,2493.11
N18312152: R197.2 U33.28 | length 101.5
  BOTTOM w6: U33.28@1973.15,2493.11 1973.15,2577.84 R197.2@1985,2589.69
N18312155: R195.2 U33.8 | length 97.3
  BOTTOM w6: U33.8@1973.15,2335.63 1973.15,2240.9 R195.2@1975,2239.05
N18312158: R194.2 U33.7 | length 128.9
  BOTTOM w6: U33.7@1998.74,2361.22 1998.74,2255.31 R194.2@2015,2239.05
N18312161: R193.2 U33.6 | length 174.5
  BOTTOM w6: U33.6@1998.74,2378.94 2018,2378.94 2030,2366.94 2030,2264.05 R193.2@2055,2239.05
N18312164: R191.2 U33.5 | length 220.3
  BOTTOM w6: U33.5@1998.74,2396.65 2037.72,2396.65 2050,2384.37 2050,2284.05 R191.2@2095,2239.05
N18312167: R190.2 U33.1 | length 272.1
  BOTTOM w6: U33.1@1998.74,2467.52 2071.85,2467.52 2090,2449.37 2090,2326.37 2102,2314.37 R190.2@2135.32,2314.37
N18314752: C166.1 C167.1 R186.2 U33.17 | length 179.1
  BOTTOM w8: 1790.32,2389.69 1795,2394.37 1813.29,2394.37 1815.57,2396.65 U33.17@1841.26,2396.65
  BOTTOM w15: R186.2@1665,2389.69 C167.1@1705,2389.69 C166.1@1745,2389.69 1790.32,2389.69
N18314935: C168.1 C169.1 R187.2 U33.16 | length 188.6
  BOTTOM w8: 1790,2359.37 1809.57,2378.94 U33.16@1841.26,2378.94
  BOTTOM w15: R187.2@1665,2349.05 C169.1@1705,2349.05 C168.1@1745,2349.05 1779.68,2349.05 1790,2359.37
N18315822: C176.1 U33.24 | length 112
  BOTTOM w8: C176.1@1865,2589.69 1865,2568.37 1902.28,2531.09 U33.24@1902.28,2493.11
N18315825: C177.1 U33.23 | length 121.3
  BOTTOM w8: C177.1@1825,2589.69 1825,2587.37 1884.57,2527.8 U33.23@1884.57,2493.11
N18315828: C178.1 U33.22 | length 141
  BOTTOM w8: C178.1@1785,2589.69 1785,2567.37 1793,2559.37 1811,2559.37 1866.85,2503.52 U33.22@1866.85,2493.11
N18315831: C179.1 U33.21 | length 172.6
  BOTTOM w8: C179.1@1745,2589.69 1745,2587.57 1787.2,2545.37 1805.2,2545.37 1841.26,2509.31 U33.21@1841.26,2467.52
N18315834: C180.1 U33.20 | length 134.1
  BOTTOM w8: C180.1@1744.68,2509.37 1780,2509.37 1790,2499.37 1790,2477.46 1796.34,2471.12 1817.66,2449.8 U33.20@1841.26,2449.8
N18315837: C181.1 U33.19 | length 112
  BOTTOM w8: C181.1@1744.68,2469.37 1778.29,2469.37 1815.57,2432.09 U33.19@1841.26,2432.09
N18315840: C182.1 U33.10 | length 97.7
  BOTTOM w8: C182.1@1935,2239.05 1937.72,2241.77 U33.10@1937.72,2335.63
N18319040: C184.1 P1.1 R196.2 R199.1 | length 201.7
  TOP w8: R196.2@2240,3029.05 R199.1@2280,3029.05 2280,3069.05 C184.1@2280.32,3069.37 2292,3081.05 2292,3158.16 P1.1@2272.44,3177.72
N18319047: C184.2 P1.2 R201.1 R202.1 | length 203.4
  TOP w8: P1.2@2327.56,3177.72 2306,3156.16 2306,3083.05 C184.2@2319.68,3069.37 2320,3069.05 R201.1@2320,3029.05 R202.1@2360,3029.05
N18319296: C183.1 R192.1 R196.1 | length 80
  TOP w10: R192.1@2160,2989.69 C183.1@2200,2989.69 R196.1@2240,2989.69
N18351323: J14.3 R76.2 | length 696.8
  BOTTOM w12: R76.2@2530,477.87 2530,454.37 2545,439.37 2545,384.37 2460,299.37 2460,174.37 2495,139.37 2630,139.37 2655,164.37 2655,226.19 2667,238.19 J14.3@2720.27,238.19
N18351325: J14.4 R77.2 | length 634.5
  BOTTOM w12: J14.4@2570.27,238.19 2623,238.19 2635,226.19 2635,171.37 2621,157.37 2505.28,157.37 2480,182.66 2480,291.08 2565,376.08 2565,434.37 2585,454.37 R77.2@2585,477.87
N18351329: J14.2 R75.2 | length 597
  BOTTOM w12: R75.2@2835,477.87 2835,454.37 2806,425.37 2806,168.37 2832.27,142.1 2918,142.1 2932,156.1 2932,219.37 2913.18,238.19 J14.2@2870.27,238.19
N18351335: J14.1 R74.2 | length 659.1
  BOTTOM w12: R74.2@2780,477.87 2780,449.37 2788,441.37 2788,156.37 2820.27,124.1 2925.46,124.1 2950,148.64 2950,219.37 2968.82,238.19 J14.1@3020.27,238.19
N18375618: D3.1 Q4.3 | length 72.8
  TOP w6: v1(437,419.37) 440,419.37 440.32,419.69 D3.1@475,419.69
  BOTTOM w6: v1(437,419.37) 440,419.37 440.32,419.69 466.18,419.69 Q4.3@470,415.87
N18375621: D3.2 R35.2 | length 65
  TOP w6: R35.2@475,294.05 D3.2@475,359.06
N18375775: Q4.1 R38.2 R41.1 | length 185.9
  BOTTOM w6: R38.2@489.68,514.37 R41.1@489.68,474.37 489.68,454.69 507.5,436.87 Q4.1@507.5,335.87
N18376132: D4.1 Q5.3 | length 96.6
  TOP w6: v1(540,419.69) D4.1@575,419.69
  BOTTOM w6: v1(540,419.69) 596.18,419.69 Q5.3@600,415.87
N18376134: D4.2 R36.2 | length 65
  TOP w6: R36.2@575,294.05 D4.2@575,359.06
N18376144: Q5.1 R39.2 R42.1 | length 185.9
  BOTTOM w6: R39.2@619.68,514.37 R42.1@619.68,474.37 637.5,456.55 Q5.1@637.5,335.87
N18437233: R235.1 U38.3 | length 91.3
  BOTTOM w6: U38.3@1024.21,3306.97 1052.4,3306.97 1060,3299.37 1060,3274.37 1065,3269.37 R235.1@1085.32,3269.37
N18438798: R236.2 R237.1 U38.4 | length 176.7
  BOTTOM w6: R236.2@804.68,3229.37 R237.1@804.68,3269.37 875,3269.37 912.6,3306.97 U38.4@925.79,3306.97
N18458541: C44.1 R30.1 R31.1 SW4.3 SW4.4 Z6.2 | length 321
  TOP w15: SW4.3@95.35,1032.9 v1(135,1032.9) SW4.4@264.65,1032.9
  BOTTOM w10: v1(135,1032.9) 136.15,1034.05 Z6.2@165,1034.05 C44.1@205,1034.05 R30.1@245,1034.05 R31.1@245,1075.32
N18458605: C45.1 R32.1 R33.1 SW5.3 SW5.4 Z7.2 | length 317.6
  TOP w15: SW5.3@95.35,1205.61 v1(137.52,1205.61) SW5.4@264.65,1205.61
  BOTTOM w8: v1(137.52,1205.61) 138.45,1204.68 Z7.2@165,1204.68 C45.1@205,1204.68 205.32,1205 R32.1@245.32,1205 R33.1@245.32,1165
N18463759: LED1.1 Q3.3 | length 103.6
  TOP w6: v1(306.5,415.87) 371.18,415.87 LED1.1@375,419.69
  BOTTOM w6: v1(306.5,415.87) Q3.3@340,415.87
N18463775: LED1.2 R34.2 | length 65
  TOP w6: R34.2@375,294.05 LED1.2@375,359.06
N18463803: Q3.1 R37.2 R40.1 | length 185.9
  BOTTOM w6: R37.2@359.68,514.37 R40.1@359.68,474.37 359.68,454.69 377.5,436.87 Q3.1@377.5,335.87
N18464833: R43.2 R45.2 U7.3 | length 120.5
  TOP w6: v1(497.44,118.86) U7.3@497.44,157.48
  BOTTOM w6: v1(497.44,118.86) 495,121.3 R43.2@495,159.69 R45.2@535,159.69
N18464854: C47.1 C48.1 R44.2 U7.2 | length 162.6
  TOP w15: v1(447.44,118.86) U7.2@447.44,157.48
  BOTTOM w10: v1(447.44,118.86) 447.44,152.13 C47.1@455,159.69
  BOTTOM w15: R44.2@375,159.69 C48.1@415,159.69 C47.1@455,159.69
N18479746: J26.1 R217.1 | length 240.9
  BOTTOM w20: J26.1@1570.7,3653.01 1638.64,3653.01 1690,3704.37 R217.1@1790.32,3704.37
N18479761: J26.3 J26.5 Q17.2 Z10.2 | length 604.9
  BOTTOM w8: Q17.2@1527.5,3052.87 1527.5,3058.87 1588,3119.37 1700,3119.37 1730,3149.37 1730,3179.05 Z10.2@1760,3209.05 1735.32,3233.73 1735.32,3256.11 J26.3@1649.44,3341.99 1578.58,3412.85 J26.5@1570.7,3412.85
N18479774: J26.2 Q16.2 R206.2 Z9.2 | length 731.5
  BOTTOM w8: J26.2@1649.44,3558.52 1649.44,3555.25 Z9.2@1775,3429.69 R206.2@1815,3429.69 1815,3394.37 1847,3362.37 1847,3136.37 1800,3089.37 1714,3089.37 Q16.2@1677.5,3052.87
N18480030: J26.4 R205.2 | length 423.2
  TOP w8: J26.4@1570.7,3180.57 1570.7,3227.37 1587.7,3244.37 1706.81,3244.37 1733,3218.18 1733,3046.05 R205.2@1750,3029.05
N18480910: C188.1 R207.2 R208.1 | length 80.5
  BOTTOM w8: R208.1@2024.68,2764.37 C188.1@2024.68,2724.37 2064.68,2724.37 R207.2@2065,2724.05
N18480944: J27.1 R219.1 | length 174.7
  BOTTOM w20: R219.1@1829.68,3654.37 2002.42,3654.37 J27.1@2003.77,3653.01
N18528085: J9.6 R52.2 | length 264.9
  BOTTOM w10: J9.6@1475.39,238.19 1475.39,304.76 1500,329.37 R52.2@1500,492.87
N18528088: J9.3 R50.2 | length 299.5
  BOTTOM w10: R50.2@1805,487.87 1805,439.37 1925.39,318.98 J9.3@1925.39,238.19
N18639472: J28.2 R212.2 U34.5 | length 694.7
  BOTTOM w8: J28.2@1186.1,3148.25 1187.59,3148.25 1231.24,3191.9 1298.43,3191.9 1315,3175.34 1315,3099.37 1220,3004.37 1220,2910.37 1174,2864.37 U34.5@1126.58,2864.37 1126.58,2822.37 1134.58,2814.37 R212.2@1205.32,2814.37
N18639500: R209.2 R212.1 U34.4 | length 159.8
  BOTTOM w8: R209.2@1244.68,2774.37 R212.1@1244.68,2814.37 1244.68,2849.05 1260,2864.37 U34.4@1323.42,2864.37
N18639545: C192.1 U34.2 U34.3 | length 218.9
  BOTTOM w6: U34.2@1323.42,2964.37 1280,2964.37 1270,2954.37 1270,2924.37 1280,2914.37 U34.3@1323.42,2914.37 1389.68,2914.37 C192.1@1395,2909.05
N18639570: C185.1 R203.2 R204.2 | length 80.5
  BOTTOM w8: R204.2@1205,2694.05 R203.2@1245,2694.05 1244.68,2694.37 C185.1@1244.68,2734.37
N18639588: C185.2 R209.1 | length 40
  BOTTOM w8: C185.2@1205.32,2734.37 R209.1@1205.32,2774.37
N18642135: C52.1 U8.2 Y1.2 | length 250.6
  BOTTOM w6: U8.2@88.39,3061.57 130.23,3061.57 170.34,3101.68 170.34,3158.71 C52.1@154.68,3174.37 135.6,3193.45 Y1.2@135.6,3239.37
N18642163: C51.1 U8.1 Y1.1 | length 275
  BOTTOM w6: U8.1@88.39,3035.98 121.61,3035.98 182.34,3096.71 182.34,3161.39 C51.1@195.32,3174.37 214.4,3193.45 Y1.1@214.4,3239.37
N18642204: C49.1 D5.3 U8.8 | length 122.8
  BOTTOM w12: U8.8@261.61,3035.98 296.29,3035.98 C49.1@315,3054.69
  BOTTOM w15: C49.1@315,3054.69 348.82,3054.69 D5.3@368.5,3074.37
N18642319: R47.2 R48.1 U8.7 | length 196.1
  BOTTOM w6: R48.1@215,2979.05 R47.2@175,2979.05 175,3039.37 197.21,3061.57 U8.7@261.61,3061.57
N18645225: Q16.3 R210.2 R211.2 | length 111.5
  BOTTOM w8: R210.2@1608.5,2874.37 1608.5,2912.55 R211.2@1620.32,2924.37 1640,2944.05 Q16.3@1640,2972.87
N18645232: Q17.3 R213.2 R215.2 | length 111.5
  BOTTOM w8: Q17.3@1490,2972.87 1490,2944.05 R215.2@1509.68,2924.37 1521.5,2912.55 R213.2@1521.5,2874.37
N18645288: C193.2 R213.1 | length 76.5
  BOTTOM w8: C193.2@1454.96,2799.37 1454.96,2870.83 R213.1@1458.5,2874.37
N18645295: C191.2 R210.1 | length 76.5
  BOTTOM w8: R210.1@1671.5,2874.37 1671.5,2802.91 C191.2@1675.04,2799.37
N18645705: C195.1 Q16.1 Q17.1 R216.2 | length 398.1
  BOTTOM w8: Q17.1@1452.5,3052.87 1489,3016.37 1566,3016.37 Q16.1@1602.5,3052.87 1639,3016.37 1747.32,3016.37 C195.1@1760,3029.05 R216.2@1800,3029.05
N18647092: J28.1 U34.8 | length 217.8
  BOTTOM w8: U34.8@1126.58,3014.37 1172,3014.37 1264.84,3107.21 J28.1@1264.84,3148.25
N18656178: C104.1 R124.2 U21.4 | length 210.6
  BOTTOM w6: R124.2@3820,3624.05 3820,3664.05 C104.1@3820.32,3664.37 3820.32,3708.37 3826.32,3714.37 3900,3714.37 3907.6,3706.77 U21.4@3907.6,3673.58
N18804334: J11.2 R63.2 | length 92.5
  TOP w12: J11.2@3787.67,538.19 3787.67,490.69 3796.5,481.86 R63.2@3796.5,449.37
N18804414: J13.2 R71.2 | length 94.5
  TOP w12: J13.2@3482.67,538.19 3482.67,490.69 3496.5,476.86 R71.2@3496.5,449.37
N18903114: C212.1 R239.1 SW6.3 SW6.4 Z12.2 | length 278.2
  TOP w15: SW6.4@95.35,1293.68 v1(137.52,1293.68) SW6.3@264.65,1293.68
  BOTTOM w8: v1(137.52,1293.68) 140.88,1290.32 Z12.2@165,1290.32 C212.1@205,1290.32 R239.1@245,1290.32
OTG_DM: D36.1 J30.A7 J30.B7 R221.1 | length 1280.5
  TOP w5.3: v1(1070,3414.37) 1080.35,3424.72 1080.35,3449.72 1087.4,3456.77 J30.A7@1087.4,3506.29 ; J30.B7@1117.32,3559.05 1117.32,3586.44 1113.84,3589.92 1113.84,3597.21 v1(1121,3604.37) 1114.15,3611.22 1114.15,3641.13 1137.39,3664.37 1221.21,3664.37 1244.51,3641.07 1379.6,3641.07 1391,3629.67 1391,3497.77 1380.9,3487.67 1348.16,3487.67 1333.85,3473.36 1333.85,3462.9 D36.1@1310,3439.05 1333.85,3415.2 1333.85,3352.9 R221.1@1320,3339.05
  ART03 w5.3: v1(1070,3414.37) 1074.85,3419.22 1074.85,3429.07 1069.55,3434.37 1047,3434.37 1022,3459.37 1022,3649.85 1043.42,3671.27 1095.1,3671.27 1117.3,3649.07 1117.3,3608.07 v1(1121,3604.37)
OTG_DP: D35.1 J30.A6 J30.B6 R220.1 | length 1321.4
  TOP w5.3: v1(1096,3414.37) 1092.65,3417.72 1092.65,3444.62 1099.7,3451.67 1099.7,3474.07 1107.08,3481.45 J30.A6@1107.08,3506.29 ; J30.B6@1097.64,3559.05 1097.64,3586.44 1101.54,3590.34 1101.54,3597.83 v1(1095,3604.37) 1101.85,3611.22 1101.85,3646.22 1132.3,3676.67 1226.3,3676.67 1249.6,3653.37 1384.7,3653.37 1403.3,3634.77 1403.3,3492.67 1386,3475.37 1353.26,3475.37 1346.15,3468.26 1346.15,3462.9 D35.1@1370,3439.05 1346.15,3415.2 1346.15,3352.9 R220.1@1360,3339.05
  ART03 w5.3: v1(1095,3604.37) 1105,3614.37 1105,3643.97 1090.01,3658.97 1048.52,3658.97 1034.3,3644.75 1034.3,3595.15 ccw(c1039.65,3595.15) 1039.65,3589.8 cw(c1039.65,3584.45) 1045,3584.45 1045,3573.95 cw(c1039.65,3573.95) 1039.65,3568.6 ccw(c1039.65,3563.25) 1034.3,3563.25 1034.3,3552.75 ccw(c1039.65,3552.75) 1039.65,3547.4 cw(c1039.65,3542.05) 1045,3542.05 1045,3531.55 cw(c1039.65,3531.55) 1039.65,3526.2 ccw(c1039.65,3520.85) 1034.3,3520.85 1034.3,3510.35 ccw(c1039.65,3510.35) 1039.65,3505 cw(c1039.65,3499.65) 1045,3499.65 1045,3489.15 cw(c1039.65,3489.15) 1039.65,3483.8 ccw(c1039.65,3478.45) 1034.3,3478.45 1034.3,3464.47 1052.1,3446.67 1074.64,3446.67 1087.15,3434.16 1087.15,3423.22 v1(1096,3414.37)
OUT1_L: C191.1 U33.12 | length 1063
  TOP w10: v1(1588,2300.37) 1590,2298.37 1590,2169.37 1612,2147.37 1758,2147.37 v1(1795,2184.37)
  BOTTOM w8: v1(1795,2184.37) 1902.28,2291.65 U33.12@1902.28,2335.63
  BOTTOM w10: v1(1588,2300.37) 1588,2782.41 C191.1@1604.96,2799.37
OUT1_R: C193.1 U33.11 | length 1167.2
  TOP w10: v1(1538,2300.37) 1540,2300.37 1560,2280.37 1560,2154.37 1590,2124.37 1770,2124.37 v1(1830,2184.37)
  BOTTOM w8: v1(1830,2184.37) 1920,2274.37 U33.11@1920,2335.63
  BOTTOM w10: C193.1@1525.04,2799.37 1525.04,2765.33 1551,2739.37 1551,2313.37 v1(1538,2300.37)
OUT2_L: R203.1 U33.15 | length 1032.3
  BOTTOM w8: R203.1@1245,2654.69 1245,2444.37 1275,2414.37 1275,2274.37 1289,2260.37 1766,2260.37 1815,2309.37 1815,2353.22 1823,2361.22 U33.15@1841.26,2361.22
